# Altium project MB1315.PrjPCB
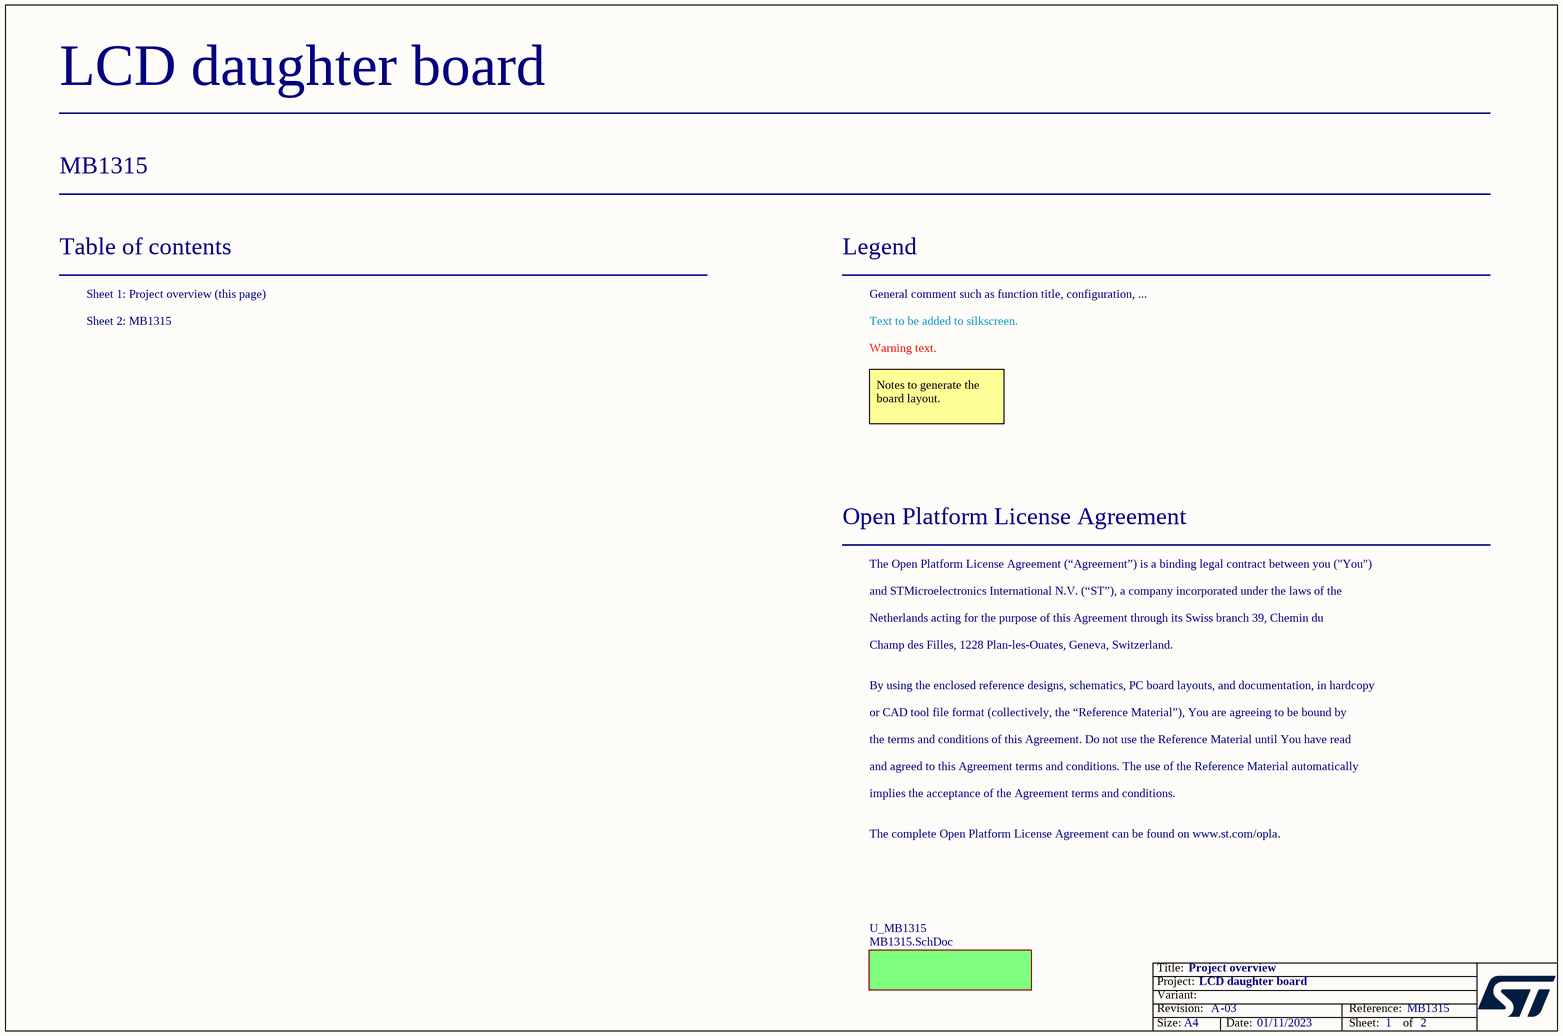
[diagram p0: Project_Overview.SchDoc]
Board_Reference: MB1315; Board_PCB_Revision: A; Board_Name: LCD daughter board; Board_Document_Date: 01/11/2023; Board_Assembly_Revision: 03
2 sheets, 37 parts. Net scope: global (net labels, ports and power ports of the same name join across sheets).
Sheets:
  Project_Overview.SchDoc
    U_MB1315 = MB1315.SchDoc

## Sheet Project_Overview.SchDoc: Project overview
size A4; Date: Not used; ApprovedBy: Not used; CheckedBy: Not used; Author: Not used; CompanyName: STMicroelectronics; DrawnBy: Not used; Engineer: Not used; Organization: Not used; Address1: Not used; Address2: Not used; Address3: Not used; Address4: Not used; DocumentNumber: 1; Revision: Not used; SheetNumber: 1; SheetTotal: 2

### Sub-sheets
U_MB1315 = MB1315.SchDoc: no entries

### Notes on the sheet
- Table of contents
- Sheet 1: Project overview (this page)
- Legend
- General comment such as function title, configuration, ...
- Sheet 2: MB1315
- Text to be added to silkscreen.
- Warning text.
- Notes to generate the board layout.
- Open Platform License Agreement
- The Open Platform License Agreement (“Agreement”) is a binding legal contract between you ("You")
- and STMicroelectronics International N.V. (“ST”), a company incorporated under the laws of the
- Netherlands acting for the purpose of this Agreement through its Swiss branch 39, Chemin du
- Champ des Filles, 1228 Plan-les-Ouates, Geneva, Switzerland.
- By using the enclosed reference designs, schematics, PC board layouts, and documentation, in hardcopy
- or CAD tool file format (collectively, the “Reference Material”), You are agreeing to be bound by
- the terms and conditions of this Agreement. Do not use the Reference Material until You have read
- and agreed to this Agreement terms and conditions. The use of the Reference Material automatically
- implies the acceptance of the Agreement terms and conditions.
- The complete Open Platform License Agreement can be found on www.st.com/opla.

## Sheet MB1315.SchDoc: RGB LCD 4.3" with Capacitive Touch
size A4; Date: 25-FEB-2015; Author: A.B; CompanyName: STMicroelectronics; Address1: 12, Rue Jules HOROWITZ; Address2: 38019 Grenoble; Address3: FRANCE; DocumentNumber: 2; Revision: A.1; SheetNumber: 2; SheetTotal: 2; Project: STM32L4Rx-EVAL Daughter board
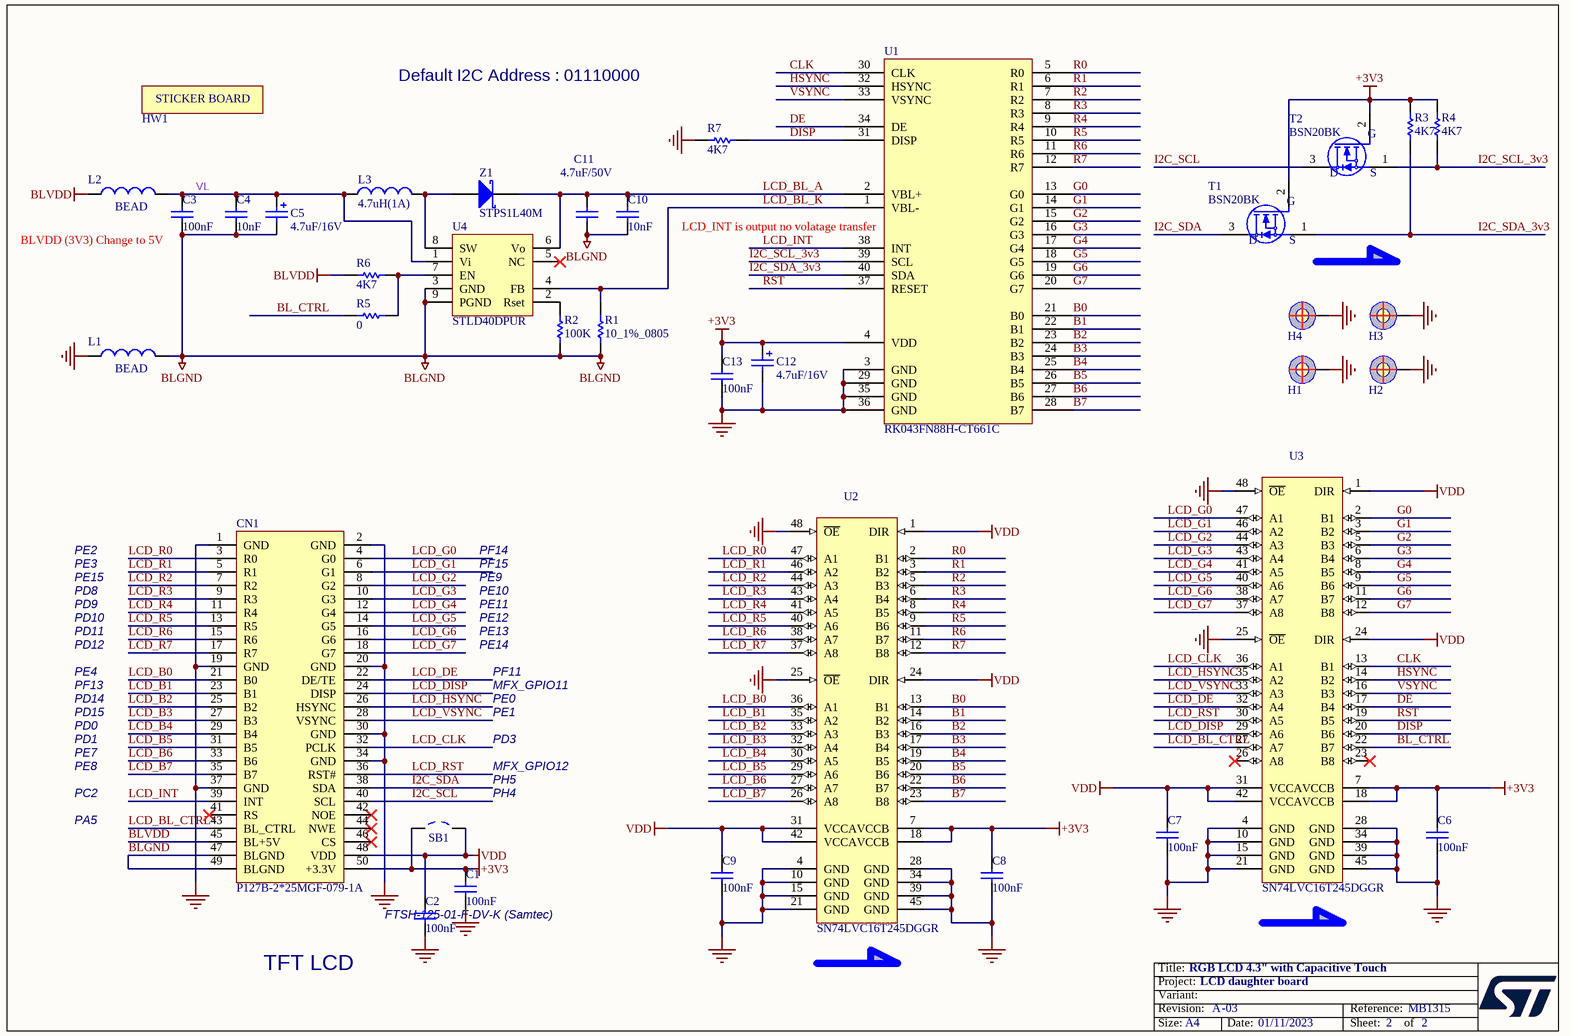
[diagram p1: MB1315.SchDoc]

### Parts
C1  100nF  [0603C]
C2  100nF  [0603C]
C3  100nF  [0603C]
C4  10nF  [0603C]
C5  4.7uF/16V  [1206C]
C6  100nF  [0603C]
C7  100nF  [0603C]
C8  100nF  [0603C]
C9  100nF  [0603C]
C10  10nF  [0603C]
C11  4.7uF/50V  [1206C]
C12  4.7uF/16V  [1206C]
C13  100nF  [0603C]
CN1  P127B-2*25MGF-079-1A  [FTSH-125-01-F-DV]
H1  POSITION HOLE  [HOLE_C9D4R5]  (value not drawn)  (no BOM)
H2  POSITION HOLE  [HOLE_C9D4R5]  (value not drawn)  (no BOM)
H3  POSITION HOLE  [HOLE_C9D4R5]  (value not drawn)  (no BOM)
H4  POSITION HOLE  [HOLE_C9D4R5]  (value not drawn)  (no BOM)
HW1  STICKER_BOARD  (value not drawn)  (no BOM)
L1  BEAD  [0603L]
L2  BEAD  [0603L]
L3  4.7uH(1A)  [1210L]
R1  10_1%_0805  [0805R]
R2  100K  [0603R]
R3  4K7  [0603R]
R4  4K7  [0603R]
R5  0  [0603R]
R6  4K7  [0603R]
R7  4K7  [0603R]
SB1  Solder Bridge OFF  [SB_0603]  (value not drawn)
T1  BSN20BK  [SOT23-213]
T2  BSN20BK  [SOT23-213]
U1  RK043FN88H-CT661C  [LCD_RK043FN48H-CT672B]
U2  SN74LVC16T245DGGR  [TSSOP48_0R5_12R5X8R1]
U3  SN74LVC16T245DGGR  [TSSOP48_0R5_12R5X8R1]
U4  STLD40DPUR  [SON8_0R65_3X3]
Z1  STPS1L40M  [DO-216AA]

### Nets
+3V3: C1.2 C6.2 C8.2 C12.1 C13.2 CN1.50(+3.3V) R3.2 R4.2 SB1.1 T1.2(G) T2.2(G) U1.4(VDD) U2.7(VCCB) U2.18(VCCB) U3.7(VCCB) U3.18(VCCB)
BLGND: C3.1 C4.1 C5.2 C10.1 C11.2 CN1.47(BLGND) CN1.49(BLGND) L1.2 R1.1 R2.1 U4.3(GND) U4.9(PGND)
BLVDD: CN1.45(BL+5V) L2.1 R6.2
GND: C1.1 C2.1 C6.1 C7.1 C8.1 C9.1 C12.2 C13.1 CN1.1(GND) CN1.2(GND) CN1.19(GND) CN1.20(GND) CN1.30(GND) CN1.34(GND) CN1.37(GND) H1.1 H2.1 H3.1 H4.1 L1.1 R7.2 U1.3(GND) U1.29(GND) U1.35(GND) U1.36(GND) U2.4(GND) U2.10(GND) U2.15(GND) U2.21(GND) U2.25(~{OE}) U2.28(GND) U2.34(GND) U2.39(GND) U2.45(GND) U2.48(~{OE}) U3.4(GND) U3.10(GND) U3.15(GND) U3.21(GND) U3.25(~{OE}) U3.28(GND) U3.34(GND) U3.39(GND) U3.45(GND) U3.48(~{OE})
VDD: C2.2 C7.2 C9.2 CN1.48(VDD) SB1.2 U2.1(DIR) U2.24(DIR) U2.31(VCCA) U2.42(VCCA) U3.1(DIR) U3.24(DIR) U3.31(VCCA) U3.42(VCCA)
B0: U1.21(B0) U2.13(B1)
B1: U1.22(B1) U2.14(B2)
B2: U1.23(B2) U2.16(B3)
B3: U1.24(B3) U2.17(B4)
B4: U1.25(B4) U2.19(B5)
B5: U1.26(B5) U2.20(B6)
B6: U1.27(B6) U2.22(B7)
B7: U1.28(B7) U2.23(B8)
BL_CTRL: R5.2 U3.22(B7)
CLK: U1.30(CLK) U3.13(B1)
DE: U1.34(DE) U3.17(B4)
DISP: R7.1 U1.31(DISP) U3.20(B6)
G0: U1.13(G0) U3.2(B1)
G1: U1.14(G1) U3.3(B2)
G2: U1.15(G2) U3.5(B3)
G3: U1.16(G3) U3.6(B4)
G4: U1.17(G4) U3.8(B5)
G5: U1.18(G5) U3.9(B6)
G6: U1.19(G6) U3.11(B7)
G7: U1.20(G7) U3.12(B8)
HSYNC: U1.32(HSYNC) U3.14(B2)
I2C_SCL: CN1.40(SCL) T2.3(D)
I2C_SCL_3v3: R4.1 T2.1(S) U1.39(SCL)
I2C_SDA: CN1.38(SDA) T1.3(D)
I2C_SDA_3v3: R3.1 T1.1(S) U1.40(SDA)
LCD_B0: CN1.21(B0) U2.36(A1)
LCD_B1: CN1.23(B1) U2.35(A2)
LCD_B2: CN1.25(B2) U2.33(A3)
LCD_B3: CN1.27(B3) U2.32(A4)
LCD_B4: CN1.29(B4) U2.30(A5)
LCD_B5: CN1.31(B5) U2.29(A6)
LCD_B6: CN1.33(B6) U2.27(A7)
LCD_B7: CN1.35(B7) U2.26(A8)
LCD_BL_A: C10.2 C11.1 U1.2(VBL+) U4.6(Vo) Z1.2(K)
LCD_BL_CTRL: CN1.43(BL_CTRL) U3.27(A7)
LCD_BL_K: R1.2 U1.1(VBL-) U4.4(FB)
LCD_CLK: CN1.32(PCLK) U3.36(A1)
LCD_DE: CN1.22(DE/TE) U3.32(A4)
LCD_DISP: CN1.24(DISP) U3.29(A6)
LCD_G0: CN1.4(G0) U3.47(A1)
LCD_G1: CN1.6(G1) U3.46(A2)
LCD_G2: CN1.8(G2) U3.44(A3)
LCD_G3: CN1.10(G3) U3.43(A4)
LCD_G4: CN1.12(G4) U3.41(A5)
LCD_G5: CN1.14(G5) U3.40(A6)
LCD_G6: CN1.16(G6) U3.38(A7)
LCD_G7: CN1.18(G7) U3.37(A8)
LCD_HSYNC: CN1.26(HSYNC) U3.35(A2)
LCD_INT: CN1.39(INT) U1.38(INT)
LCD_R0: CN1.3(R0) U2.47(A1)
LCD_R1: CN1.5(R1) U2.46(A2)
LCD_R2: CN1.7(R2) U2.44(A3)
LCD_R3: CN1.9(R3) U2.43(A4)
LCD_R4: CN1.11(R4) U2.41(A5)
LCD_R5: CN1.13(R5) U2.40(A6)
LCD_R6: CN1.15(R6) U2.38(A7)
LCD_R7: CN1.17(R7) U2.37(A8)
LCD_RST: CN1.36(RST#) U3.30(A5)
LCD_VSYNC: CN1.28(VSYNC) U3.33(A3)
R0: U1.5(R0) U2.2(B1)
R1: U1.6(R1) U2.3(B2)
R2: U1.7(R2) U2.5(B3)
R3: U1.8(R3) U2.6(B4)
R4: U1.9(R4) U2.8(B5)
R5: U1.10(R5) U2.9(B6)
R6: U1.11(R6) U2.11(B7)
R7: U1.12(R7) U2.12(B8)
RST: U1.37(RESET) U3.19(B5)
VL: C3.2 C4.2 C5.1 L2.2 L3.1 U4.1(Vi)
VSYNC: U1.33(VSYNC) U3.16(B3)
NetL3_2: L3.2 U4.8(SW) Z1.1(A)
NetR2_2: R2.2 U4.2(Rset)
NetR5_1: R5.1 R6.1 U4.7(EN)

Not connected (* = marked no-connect by the designer): CN1 41(RS)* 42(NOE)* 44(NWE)* 46(CS)*; U3 23(B8)* 26(A8)*; U4 5(NC)*

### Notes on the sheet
- Default I2C Address : 01110000
- (near C3) BLVDD (3V3) Change to 5V
- (near U1) LCD_INT is output no volatage transfer
- PE2
- PE3
- PE15
- PF14
- PF15
- PE9
- PD8
- PD9
- PD10
- PD11
- PD12
- PE10
- PE11
- PE12
- PE13
- PE14
- PE4
- PF13
- PD14
- PD15
- PF11
- PE0
- PE1
- MFX_GPIO11
- PD0
- PD1
- PE7
- PE8
- PD3
- PH5
- MFX_GPIO12
- PC2
- PA5
- (near SB1) PH4
- FTSH-125-01-F-DV-K (Samtec)
- TFT LCD

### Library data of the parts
C1 C2 C6-C9 C13 = CAP: Capacitor; Value: 100pF; Ordered by: Subcon; ECCN_US/EU: NA
C3 = Cap_100nF_X7R_10%_0603: Capacitor,100nF,16V,X7R,10%,0603,YAGEO; Manuf_Part_1: CC0603KRX7R9BB104
C4 C10 = Cap_10nF_X7R_10%_0603: Capacitor,10nF,50V,X7R,10%,0603,YAGEO; Manuf_Part_1: CC0603KRX7R9BB103
C5 = Cap Pol1: Polarized Capacitor (Radial); Manuf_Part_1: CC1206KKX7R7BB475; Manuf_1: YAGEO; Value: 100pF; Ordered by: Subcon; ECCN_US/EU: NA
C11 = CAP: Capacitor; Manuf_Part_1: CC1206KKX7R9BB475; Manuf_1: YAGEO; Ordered by: Subcon; ECCN_US/EU: NA
C12 = Cap Pol1: Polarized Capacitor (Radial); Manuf_1: YAGEO; Manuf_Part_1: CC1206KKX7R7BB475; Value: 100pF; Ordered by: Subcon; ECCN_US/EU: NA
CN1 = Header 25X2: TFT LCD connector
H1-H4 = POSITION HOLE: Fitted: NO
L1 L2 = Inductor: Manuf_1: Tai-tech; Manuf_Part_1: FCM1608KF-601T03; Value: 100uH; Ordered by: Subcon; ECCN_US/EU: NA
L3 = Inductor: Manuf_1: Murata; Manuf_Part_1: LQH32PN4R7NN0L; Ordered by: Subcon; ECCN_US/EU: NA
R1 = Res_10_1%_0805: Resistor,10,0805,1%,Stackpole,1/4W; Manuf_Part_1: RNCP0805FTD10R0; Manuf_1: Stackpole Electronics Inc; Value: 10
R2 = Res_1K_1%_0603: Resistor,100K,0603,1%,YAGEO; Manuf_Part_1: RC0603FR-07100KL; Ordered by: Subcon; Fitted: YES
R3 R4 R6 R7 = Res_1K_1%_0603: Resistor,4.7K,0603,1%,YAGEO; Manuf_Part_1: RC0603FR-074K7L; Ordered by: Subcon; Fitted: YES
R5 = Res_1K_1%_0603: Resistor,0K,0603,1%,YAGEO; Manuf_Part_1: RC0603JR-070RL; Ordered by: Subcon; Fitted: YES
SB1 = SB_OFF: Fitted: YES; Ordered by: Subcon
T1 T2 = 2N7000: Manuf_1: NEXPERIA; ECCN_US/EU: EAR99/NEC
U1 = RK043FN48H-CT672B: LCD,  TFT, 4.3 inch, 480x272 pixels with LED Backlight and Capacitive touch panel, high luminance with 0.5mm pitch flat cable; Manuf_1: ROCKTECH; Manuf_Part_1: RK043FN78HV-CT661C
U2 U3 = SN74LVC16T245: Manuf_1: TI; Ordered by: Subcon; ECCN_US/EU: EAR99/NEC
U4 = STLD40DPUR: White LED power supply for large display backlight, QFN8; Ordered by: STM; ECCN_US/EU: EAR99/NEC; Ref St: xxxxxxxxx; Provided: ST
Z1 = D Schottky: Schottky Diode; Code - JEDEC: DO-214-AA; Ordered by: STM; Ref St: 9151085; ECCN_US/EU: EAR99/NEC

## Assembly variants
Default: not fitted H1 H2 H3 H4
